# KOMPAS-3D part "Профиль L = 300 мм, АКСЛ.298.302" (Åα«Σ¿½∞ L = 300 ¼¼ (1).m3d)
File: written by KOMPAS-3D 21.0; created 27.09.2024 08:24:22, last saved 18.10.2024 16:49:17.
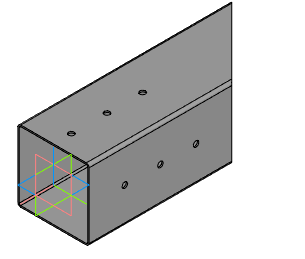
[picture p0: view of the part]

Document properties: Полное имя файла: C:\Users\Алексей Бочаров\YandexDisk\Соединения бруса\Соединения бруса\ТРИО\Профиль L = 300 мм (1).m3d; Автор: Алексей Бочаров

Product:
- Part/product: Профиль L = 300 мм  | designation АКСЛ.298.302
    Масса: 1.514806
    Форматы листов документа: A2

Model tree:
1. Эскиз:1
2. Элемент выдавливания:1
     Расстояние 2 = 300
3. Плоскость под углом:1  (with: Элемент выдавливания:1)
     Угол = 45
4. Разрезать:1
5. Эскиз:2  (with: Разрезать:1)
6. Элемент выдавливания:2  (with: Разрезать:1)
7. Эскиз:3  (with: Разрезать:1)
8. Элемент выдавливания:3  (with: Разрезать:1)
     Расстояние 2 = 2

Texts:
  АКСЛ.298.302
